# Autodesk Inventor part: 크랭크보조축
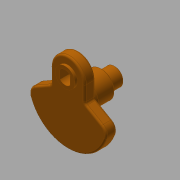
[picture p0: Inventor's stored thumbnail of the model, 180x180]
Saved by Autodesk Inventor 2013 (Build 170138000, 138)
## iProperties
Created: 2016-11
Part Number: 크랭크보조축
Material: 강철, 탄소
Document SubType Name: Modeling
Designer: mduedu
Density: 7.87 g/cm^3
Mass: 629.242 g
Surface Area: 163.688 cm^2
Volume: 79.9545 cm^3
Author: mduedu
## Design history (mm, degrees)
sketch "스케치1" dims "d8" = 65
  geometry: L1 (-19, 26.368)-(-19, 8.368); L2 (-19, 8.368)-(-44.545, -6.381); L3 (0, 26.368)-(0, -45); L4 (19, 26.368)-(19, 8.368); L5 (19, 8.368)-(44.545, -6.381); C1 r 10 at (0, 0); C2 r 17.5 at (0, 0); A1 r 45 centre (0, 0) between (-44.545, -6.381) and (0, -45); A2 r 19 centre (0, 26.368) between (0, 45.368) and (-19, 26.368); A3 r 19 centre (0, 26.368) between (19, 26.368) and (0, 45.368); A4 r 45 centre (0, 0) between (0, -45) and (44.545, -6.381); 2 further points
  constraints: 10 end point, 8 point on circle, 6 centre point, 4 coincident, 3 symmetric about line, 2 point on line, 1 parallel, 1 tangent, 1 vertical, 1 vertical alignment, 5 other
  dimensions: "d1" = 20 diameter of C1; "d2" = 35 diameter of C2; "d4" = 18 distance of L1.start L1.end; "d5" = 120 deg angle of L2 L1; "d6" = 45 radius of A1; "d9" = 19 radius of A2
extrude "돌출1" new body sketch "스케치1" distance "d10" = 12; taper "d11" = 0 deg
sketch "스케치2"
  geometry: C1 r 7.5 at (0, 26.368); C2 r 11 at (0, 26.368); A1 r 19 centre (0, 26.368) between (19, 26.368) and (-19, 26.368) reference; 1 further point
  constraints: 2 centre point, 2 coincident
  dimensions: "d16" = 15 diameter of C1; "d17" = 22 diameter of C2
extrude "돌출10" join sketch "스케치1" distance "d46" = 5; taper "d47" = 0 deg
extrude "돌출11" join sketch "스케치1" distance "d48" = 41; taper "d49" = 0 deg
extrude "돌출12" join sketch "스케치2" distance "d50" = 3; taper "d51" = 0 deg
extrude "돌출13" cut sketch "스케치2" stored distance "d52" = 3; taper "d53" = 0 deg
sketch "스케치7"
  geometry: L1 (5.75, -4.815)-(-5.75, -4.815); L2 (-5.75, -4.815)-(-5.75, 4.815); L3 (-5.75, 4.815)-(5.75, 4.815); L4 (5.75, 4.815)-(5.75, -4.815); L5 (5.75, -4.815)-(-5.75, 4.815); L6 (-5.75, -4.815)-(5.75, 4.815); A1 r 7.5 centre (0, 0) between (-5.75, 4.815) and (-5.75, -4.815); A2 r 7.5 centre (0, 0) between (5.75, -4.815) and (5.75, 4.815); 2 further points
  constraints: 12 end point, 4 point on circle, 2 centre point, 2 midpoint, 2 parallel, 1 coincident, 1 horizontal, 1 perpendicular, 2 other
  dimensions: "d54" = 11.5 distance of L2.end L3.end
extrude "돌출14" join sketch "스케치7" stored distance "d56" = 40.75; taper "d57" = 0 deg
sketch "스케치8"
  geometry: C1 r 17.5 at (0, 0) reference; C2 r 15 at (0, 0); 1 further point
  constraints: 1 centre point, 1 coincident
  dimensions: "d58" = 30 diameter of C2
extrude "돌출15" join sketch "스케치8" distance "d59" = 21; taper "d60" = 0 deg
chamfer "모따기3" distance "d61" = 1; stored, may be unused: second distance "d62" = 2, angle "d63" = 45 deg
fillet "모깎기3" dims "d64" = 3, "d65" = 10
fillet "모깎기4" dims "d66" = 2
node "솔리드1"
other parameters: "d3" = 38
